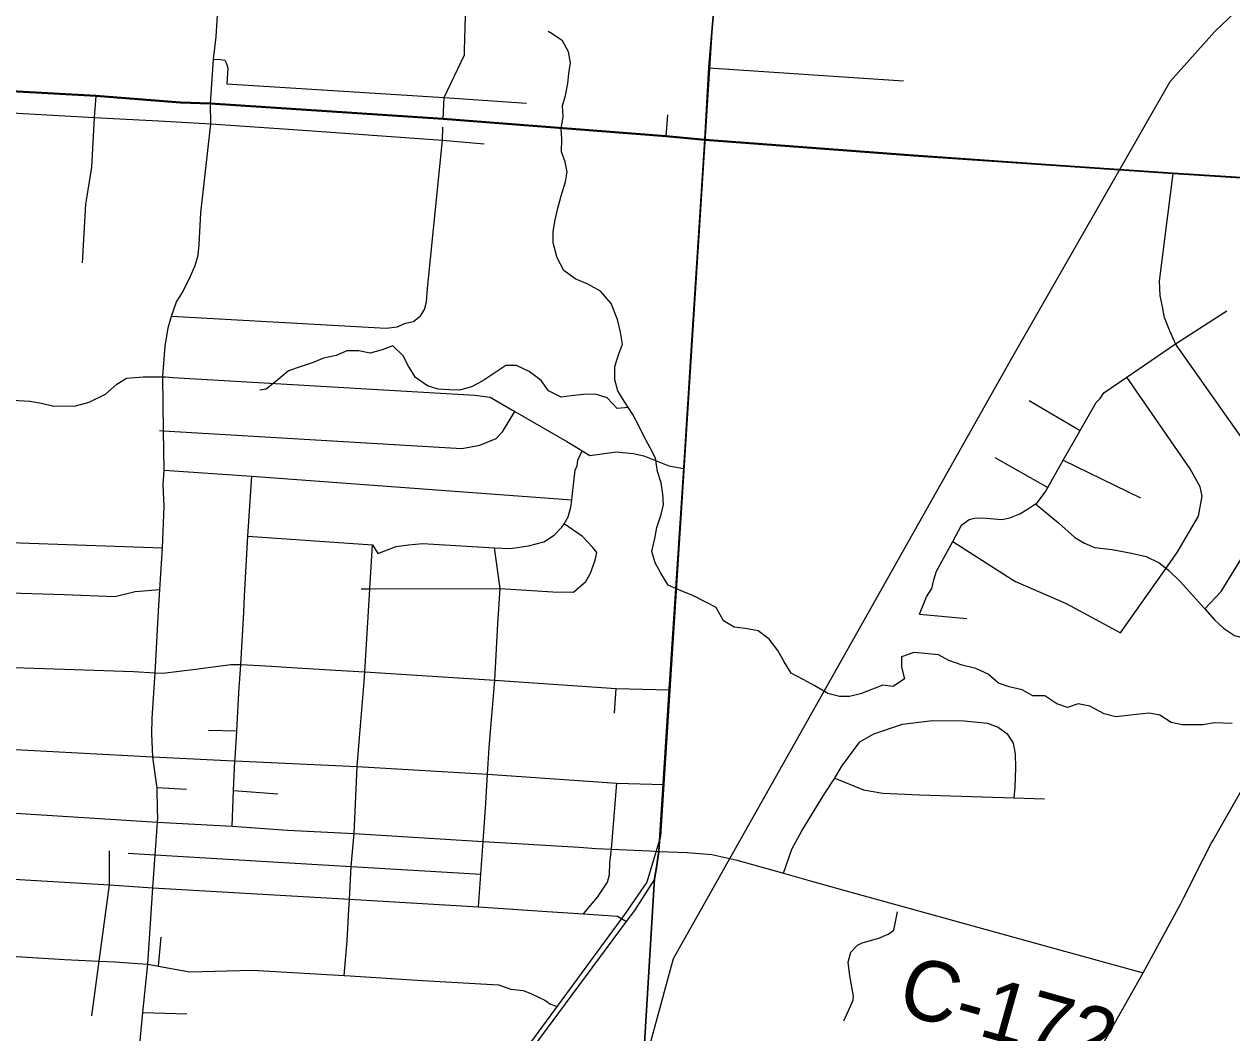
# Model space of a CAD drawing. Extents: x 0 to 34, y 0 to 22.
# Drawn here: x 3.011 to 4.152, y 15.572 to 16.524 of the extents above; entities that cross this region are included whole.
import ezdxf

# ---------------------------------------------------------------- set-up
doc = ezdxf.new("R2010")
doc.units = 0
for name, color, linetype in [('GM_X_City_Street', 7, 'Continuous'), ('GM_X_County_Road', 7, 'Continuous'), ('GM_X_County_Road_Text', 7, 'Continuous'), ('GM_X_Minor_River', 7, 'Continuous'), ('GM_X_Rail_Line', 7, 'Continuous'), ('GM_X_State_Route', 7, 'Continuous'), ('GM_X_Township_Road', 7, 'Continuous')]:
    doc.layers.add(name, color=color, linetype=linetype)

msp = doc.modelspace()

# ---------------------------------------------------------------- linework, layer by layer
at = {"layer": 'GM_X_City_Street'}
for p, q in [((3.4269, 16.4995), (3.428, 16.5321)), ((3.0775, 16.4361), (3.079, 16.4564)), ((3.6175, 16.4183), (3.6189, 16.4387)), ((4.0986, 16.2224), (4.1471, 16.2536)), ((3.9604, 16.1688), (4.0084, 16.1404)), ((3.9278, 16.1152), (3.9779, 16.0868)), ((3.9925, 16.1125), (4.0656, 16.0771)), ((3.8568, 15.9672), (3.9015, 15.963)), ((3.3133, 15.6258), (3.316, 15.6584))]:
    msp.add_line(p, q, dxfattribs=at)
for points in [[(3.1869, 16.4491), (3.1898, 16.4914), (3.1922, 16.5124), (3.194, 16.5377), (3.1953, 16.5587), (3.1958, 16.5715), (3.1963, 16.5771), (3.1976, 16.5817), (3.1996, 16.5875), (3.2022, 16.5935), (3.2063, 16.5999), (3.2107, 16.6054), (3.2295, 16.6239), (3.2699, 16.661), (3.3316, 16.7186), (3.3479, 16.7335), (3.3529, 16.7386), (3.3582, 16.7457), (3.3587, 16.7466)], [(3.4067, 16.4347), (3.4077, 16.4551), (3.4268, 16.4954), (3.4269, 16.4995)], [(3.1898, 16.4914), (3.1965, 16.4909), (3.2004, 16.4903), (3.202, 16.4871), (3.2033, 16.4827), (3.2024, 16.4681), (3.4077, 16.4551), (3.4854, 16.4498)], [(2.8272, 16.4501), (2.8851, 16.4478), (3.0099, 16.44), (3.0775, 16.4361), (3.1074, 16.4346), (3.1381, 16.433), (3.1874, 16.4301), (3.2697, 16.4245), (3.406, 16.4147), (3.4454, 16.4112)], [(3.138, 15.9699), (3.1391, 15.9904), (3.1417, 16.0298), (3.1432, 16.0688), (3.1422, 16.0892), (3.1431, 16.103), (3.1426, 16.1403), (3.1419, 16.1912), (3.1419, 16.192), (3.144, 16.2201), (3.147, 16.2375), (3.1501, 16.2486), (3.1547, 16.262), (3.1606, 16.271), (3.1681, 16.2864), (3.1725, 16.2965), (3.1754, 16.3063), (3.1764, 16.3162), (3.1778, 16.3461), (3.1874, 16.4301), (3.1869, 16.4491)], [(3.0698, 16.3582), (3.075, 16.3891), (3.0775, 16.4361)], [(3.3787, 16.2435), (3.3853, 16.2487), (3.3892, 16.2547), (3.3909, 16.2622), (3.3919, 16.2747), (3.406, 16.4147), (3.4063, 16.427)], [(4.1263, 15.972), (4.1418, 15.9884), (4.1819, 16.054), (4.1887, 16.0728), (4.1886, 16.0823), (4.1879, 16.0892), (4.1862, 16.0972), (4.1789, 16.1087), (4.1679, 16.1242), (4.0986, 16.2224), (4.0922, 16.237), (4.0882, 16.2473), (4.0865, 16.2557), (4.0841, 16.2679), (4.0836, 16.2816), (4.0963, 16.3832)], [(3.0661, 16.2988), (3.0691, 16.3543), (3.0698, 16.3582)], [(3.1501, 16.2486), (3.3528, 16.2372), (3.3634, 16.2385), (3.3711, 16.2418), (3.3787, 16.2435)], [(3.8568, 15.9672), (3.8615, 15.9788), (3.8634, 15.9835), (3.8683, 15.9912), (3.8704, 15.9995), (3.8728, 16.0078), (3.8881, 16.0358), (3.8965, 16.051), (3.9038, 16.0565), (3.9087, 16.0579), (3.9163, 16.0582), (3.9345, 16.0566), (3.9421, 16.058), (3.9516, 16.0619), (3.9589, 16.0663), (3.9664, 16.0714), (3.9682, 16.0726), (3.976, 16.0834), (3.9779, 16.0868), (3.9925, 16.1125), (4.0084, 16.1404), (4.0236, 16.1671), (4.0275, 16.1708), (4.031, 16.176), (4.0527, 16.1909), (4.0986, 16.2224)], [(2.8281, 16.1733), (2.8316, 16.1766), (2.8376, 16.1773), (2.8456, 16.1779), (3.0163, 16.1681), (3.0273, 16.1664), (3.039, 16.1635), (3.0594, 16.1638), (3.0724, 16.1673), (3.0877, 16.175), (3.0985, 16.1842), (3.1077, 16.1901), (3.1233, 16.1913), (3.1419, 16.1912), (3.1426, 16.1912), (3.1446, 16.1911), (3.1515, 16.1907)], [(3.1515, 16.1907), (3.4367, 16.1739), (3.4511, 16.1721), (3.4604, 16.1666), (3.4744, 16.1586), (3.5237, 16.1303), (3.5361, 16.1225), (3.538, 16.1213), (3.5454, 16.117), (3.5702, 16.1205), (3.5862, 16.1189), (3.5962, 16.1167), (3.6058, 16.1127), (3.62, 16.1071), (3.6342, 16.1048)], [(4.0467, 15.9494), (4.0897, 16.0105), (4.1002, 16.0254), (4.1202, 16.0595), (4.1237, 16.0784), (4.122, 16.0872), (4.1125, 16.1044), (4.0527, 16.1909)], [(3.1387, 16.1405), (3.1426, 16.1403), (3.4243, 16.1237), (3.4414, 16.1268), (3.4567, 16.1329), (3.4629, 16.1392), (3.4744, 16.1586)], [(3.2222, 16.0406), (3.34, 16.0327), (3.3449, 16.0244), (3.3624, 16.0309), (3.3739, 16.0326), (3.3871, 16.0338), (3.4552, 16.0298), (3.47, 16.029), (3.4875, 16.0316), (3.502, 16.0355), (3.5116, 16.0418), (3.519, 16.0492), (3.521, 16.0525), (3.5249, 16.0589), (3.5273, 16.068), (3.5283, 16.0751), (3.5291, 16.0812), (3.5315, 16.1032), (3.5335, 16.1073), (3.534, 16.1126), (3.538, 16.1213)], [(3.1431, 16.103), (3.2259, 16.0973), (3.5283, 16.0751)], [(3.2184, 15.9687), (3.2192, 15.9844), (3.2222, 16.0406), (3.2259, 16.0973)], [(3.9664, 16.0714), (3.9882, 16.0532), (4.0035, 16.0396), (4.0125, 16.0341), (4.0222, 16.0301), (4.0389, 16.0282), (4.057, 16.0248), (4.0709, 16.0214), (4.0833, 16.0155), (4.089, 16.011), (4.0897, 16.0105), (4.0922, 16.0084), (4.103, 15.998), (4.1263, 15.972), (4.1356, 15.9616), (4.1438, 15.9538), (4.1542, 15.9468), (4.1663, 15.9438), (4.1746, 15.9429), (4.1997, 15.9465), (4.2058, 15.9468), (4.2122, 15.9455), (4.2368, 15.9393)], [(3.3293, 15.991), (3.3374, 15.991), (3.4605, 15.9913), (3.5104, 15.9881), (3.5298, 15.9878), (3.5414, 15.9978), (3.5461, 16.0057), (3.5505, 16.0181), (3.5518, 16.0253), (3.5481, 16.03), (3.5385, 16.0404), (3.521, 16.0525)], [(2.8209, 16.0408), (2.9795, 16.0354), (3.1417, 16.0298)], [(3.3358, 15.9647), (3.3374, 15.991), (3.34, 16.0327)], [(3.4583, 15.958), (3.4605, 15.9913), (3.4552, 16.0298)], [(3.8881, 16.0358), (3.9443, 15.9998), (3.9476, 15.9979), (3.9953, 15.9771), (4.0467, 15.9494)], [(2.8235, 15.9931), (2.9766, 15.988), (3.0492, 15.9858), (3.0966, 15.9839), (3.1159, 15.9886), (3.1391, 15.9904)], [(3.3244, 15.7949), (3.3256, 15.8231), (3.3275, 15.8466)], [(3.4471, 15.7885), (3.4487, 15.8161), (3.4502, 15.8411)], [(3.2027, 15.829), (3.2101, 15.8287), (3.3256, 15.8231), (3.4487, 15.8161), (3.5708, 15.8076), (3.6148, 15.8062)], [(3.167, 15.6292), (3.2266, 15.6309), (3.3133, 15.6258), (3.314, 15.6258), (3.3873, 15.6212), (3.4591, 15.6171), (3.4707, 15.6129), (3.4824, 15.6115), (3.4895, 15.6087), (3.4974, 15.6051), (3.5027, 15.6024), (3.5083, 15.5988), (3.5135, 15.5968)]]:
    msp.add_lwpolyline(points, dxfattribs=at)
at = {"layer": 'GM_X_County_Road'}
msp.add_line((3.5657, 15.7451), (3.6017, 15.7434), dxfattribs=at)
for points in [[(2.884, 16.4676), (3.0788, 16.4569), (3.1585, 16.4507), (3.1867, 16.4496), (3.4065, 16.4352), (3.6172, 16.4188), (3.654, 16.4154), (3.6577, 16.4837), (3.663, 16.546), (3.6669, 16.6092), (3.6708, 16.6723), (3.6747, 16.7338), (3.6783, 16.7921), (3.682, 16.8509), (3.6854, 16.9064), (3.686, 16.9146), (3.6886, 16.9563), (3.6945, 17.0525), (3.6989, 17.1221), (3.6998, 17.1375), (3.7021, 17.1741), (3.7063, 17.2218), (3.7066, 17.225), (3.7101, 17.3019)], [(3.7101, 17.3019), (3.7066, 17.225), (3.7063, 17.2218), (3.7021, 17.1741), (3.6998, 17.1375), (3.6989, 17.1221), (3.6945, 17.0525), (3.6886, 16.9563), (3.686, 16.9146), (3.6854, 16.9064), (3.682, 16.8509), (3.6783, 16.7921), (3.6747, 16.7338), (3.6708, 16.6723), (3.6669, 16.6092), (3.663, 16.546), (3.6577, 16.4837), (3.654, 16.4154), (3.8512, 16.4005), (3.9805, 16.3916), (4.0961, 16.3837), (4.4809, 16.3594)], [(3.6542, 16.4148), (3.6579, 16.4832), (3.6632, 16.5454), (3.6671, 16.6087), (3.6711, 16.6718), (3.6749, 16.7333), (3.6785, 16.7915), (3.6822, 16.8503), (3.6857, 16.9058), (3.6862, 16.914), (3.6888, 16.9558), (3.6948, 17.052), (3.6991, 17.1215), (3.7001, 17.1369), (3.7024, 17.1735), (3.7065, 17.2213), (3.7068, 17.2244), (3.7103, 17.3014)], [(2.1, 16.5138), (2.2437, 16.5027), (2.3644, 16.4926), (2.533, 16.4821), (2.7036, 16.4747), (2.8842, 16.467), (3.079, 16.4564), (3.1587, 16.4501), (3.1869, 16.4491), (3.4067, 16.4347), (3.6175, 16.4183), (3.6542, 16.4148)], [(5.4989, 16.2977), (5.2615, 16.3089), (5.0301, 16.3238), (4.7825, 16.3404), (4.4809, 16.3594), (4.0961, 16.3837), (3.9805, 16.3916), (3.8512, 16.4005), (3.654, 16.4154), (3.6418, 16.2257), (3.634, 16.1053), (3.6204, 15.8961), (3.6146, 15.8068), (3.6105, 15.7435), (3.6083, 15.7281), (3.6065, 15.7173), (3.5547, 14.8664), (3.5412, 14.6736), (3.5067, 14.1788), (3.5033, 14.1), (8.2619, 14.1)], [(3.6168, 15.836), (3.6206, 15.8956), (3.6342, 16.1048), (3.642, 16.2252), (3.6542, 16.4148)], [(3.6542, 16.4148), (3.8515, 16.3999), (3.9807, 16.3911), (4.0963, 16.3832), (4.4811, 16.3588)], [(3.4766, 15.5374), (3.5224, 15.599), (3.5801, 15.6767), (3.5879, 15.6873), (3.6067, 15.7167), (3.6085, 15.7276), (3.6107, 15.7429), (3.6148, 15.8062), (3.6168, 15.836)], [(2.7826, 15.7922), (2.7921, 15.7915), (2.8726, 15.7865), (2.9627, 15.7816), (3.1368, 15.7707), (3.2073, 15.7668), (3.2598, 15.7632), (3.3228, 15.7599), (3.4447, 15.7525), (3.5351, 15.7469)], [(3.5351, 15.7469), (3.5512, 15.7459), (3.5657, 15.7451)], [(3.6017, 15.7434), (3.6107, 15.7429), (3.6374, 15.7419), (3.6605, 15.74), (3.6834, 15.735), (3.7283, 15.7224), (3.7546, 15.715), (3.7773, 15.7087), (3.7783, 15.7084)], [(3.7783, 15.7084), (3.9754, 15.6538), (4.0681, 15.6282)]]:
    msp.add_lwpolyline(points, dxfattribs=at)
msp.add_lwpolyline([(2.1, 16.5143), (2.1, 14.1), (3.5033, 14.1), (3.5067, 14.1788), (3.5412, 14.6736), (3.5547, 14.8664), (3.6065, 15.7173), (3.6083, 15.7281), (3.6105, 15.7435), (3.6146, 15.8068), (3.6204, 15.8961), (3.634, 16.1053), (3.6418, 16.2257), (3.654, 16.4154), (3.6172, 16.4188), (3.4065, 16.4352), (3.1867, 16.4496), (3.1585, 16.4507), (3.0788, 16.4569), (2.884, 16.4676), (2.7034, 16.4752), (2.5328, 16.4826), (2.3641, 16.4932), (2.2435, 16.5033)], close=True, dxfattribs=at)
at = {"layer": 'GM_X_Minor_River'}
for points in [[(3.6923, 15.9536), (3.6817, 15.9549), (3.6715, 15.9607), (3.6648, 15.9733), (3.655, 15.9783), (3.6433, 15.9845), (3.6316, 15.9891), (3.6192, 15.9946), (3.6124, 16.0057), (3.6072, 16.0156), (3.6039, 16.0262), (3.6067, 16.0384), (3.6087, 16.049), (3.6126, 16.0611), (3.6149, 16.0706), (3.6143, 16.0805), (3.6128, 16.0911), (3.6091, 16.1018), (3.6074, 16.1143), (3.6022, 16.1243), (3.5962, 16.1353), (3.5914, 16.1456), (3.5861, 16.1555), (3.5779, 16.1682), (3.5719, 16.1781), (3.569, 16.1884), (3.5691, 16.2009), (3.5723, 16.2119), (3.5761, 16.2221), (3.5743, 16.2335), (3.5714, 16.2453), (3.5655, 16.2606), (3.5554, 16.2721), (3.5433, 16.2786), (3.5316, 16.2837), (3.5207, 16.2918), (3.5144, 16.3036), (3.5107, 16.3177), (3.5108, 16.3283), (3.5124, 16.3378), (3.5148, 16.3492), (3.5183, 16.3621), (3.5222, 16.3753), (3.5238, 16.3848), (3.522, 16.3943), (3.5187, 16.4038), (3.5188, 16.416), (3.5181, 16.4255), (3.5201, 16.4372), (3.5195, 16.4471), (3.5222, 16.457), (3.5246, 16.4683), (3.5254, 16.4778), (3.527, 16.4877), (3.5252, 16.4983), (3.5196, 16.5087), (3.5099, 16.5152), (3.5061, 16.5175)], [(3.5818, 16.1622), (3.571, 16.1614), (3.5617, 16.1714), (3.5507, 16.1749), (3.5393, 16.1746), (3.5276, 16.1732), (3.5181, 16.1721), (3.5064, 16.1779), (3.4993, 16.1879), (3.488, 16.1964), (3.4759, 16.2018), (3.466, 16.2019), (3.4443, 16.1876), (3.4336, 16.1817), (3.4222, 16.1787), (3.4128, 16.1788), (3.4022, 16.1797), (3.392, 16.1828), (3.3807, 16.1905), (3.3739, 16.2012), (3.3691, 16.2111), (3.3593, 16.2204), (3.3491, 16.2166), (3.3377, 16.2137), (3.3271, 16.2157), (3.3157, 16.2158), (3.3058, 16.2114), (3.2937, 16.2088), (3.2841, 16.2047), (3.2716, 16.2007), (3.2606, 16.197), (3.2506, 16.1883), (3.2396, 16.1797), (3.2335, 16.1786)], [(4.152, 15.8639), (4.1353, 15.8644), (4.1243, 15.8626), (4.1144, 15.8627), (4.105, 15.8624), (4.0944, 15.8648), (4.0838, 15.8717), (4.0736, 15.8737), (4.0619, 15.8723), (4.0421, 15.8702), (4.0312, 15.873), (4.0176, 15.8803), (4.0066, 15.8823), (3.9967, 15.879), (3.9865, 15.8825), (3.9752, 15.8898), (3.9639, 15.8899), (3.9537, 15.8957), (3.9416, 15.8985), (3.9314, 15.902), (3.9216, 15.9105), (3.9099, 15.9159), (3.897, 15.919), (3.8846, 15.9233), (3.8748, 15.9288), (3.8619, 15.93), (3.8513, 15.9309), (3.8399, 15.9268), (3.8398, 15.9169), (3.8427, 15.9059), (3.832, 15.8988), (3.8222, 15.9), (3.8123, 15.8963), (3.8009, 15.8918), (3.7906, 15.8893), (3.7812, 15.8894), (3.7702, 15.8921), (3.7578, 15.8995), (3.7468, 15.9053), (3.7355, 15.9115), (3.7288, 15.9221), (3.7228, 15.9328), (3.7146, 15.9436), (3.7044, 15.9512), (3.6923, 15.9536)]]:
    msp.add_lwpolyline(points, dxfattribs=at)
at = {"layer": 'GM_X_Rail_Line'}
for points in [[(3.7202, 17.4495), (3.6121, 15.7571), (3.5991, 15.7141), (3.5781, 15.6833), (3.3718, 15.4026), (3.2933, 15.2964), (3.27, 15.2612), (3.26, 15.2394), (3.2447, 15.1962), (3.2204, 15.1356), (3.1206, 14.8429), (3.107, 14.7951), (3.0878, 14.7358), (3.0717, 14.6527), (3.0679, 14.583), (3.0599, 14.4798), (3.0531, 14.3964), (3.0341, 14.1)], [(3.2263, 14.1), (3.3201, 14.4671), (3.4798, 15.0811), (3.5889, 15.5111), (3.6244, 15.6418), (3.9439, 16.2089), (4.0935, 16.4703), (4.1354, 16.5172), (4.1886, 16.568), (4.5538, 16.8382), (4.6413, 16.9169), (4.6831, 16.9702), (4.73, 17.0374), (4.7604, 17.097), (4.7896, 17.177), (4.8023, 17.2505), (4.8213, 17.366)]]:
    msp.add_lwpolyline(points, dxfattribs=at)
at = {"layer": 'GM_X_State_Route'}
msp.add_line((4.1064, 15.6994), (4.1248, 15.7356), dxfattribs=at)
for points in [[(4.1341, 15.7536), (4.1589, 15.7966), (4.1642, 15.8063)], [(4.1248, 15.7356), (4.1326, 15.751), (4.1341, 15.7536)], [(4.0681, 15.6282), (4.1032, 15.6931), (4.1064, 15.6994)], [(3.9411, 15.4018), (3.9506, 15.4193), (3.9861, 15.4829), (4.0275, 15.5564), (4.0681, 15.6282)]]:
    msp.add_lwpolyline(points, dxfattribs=at)
at = {"layer": 'GM_X_Township_Road'}
for p, q in [((3.6579, 16.4832), (3.8415, 16.4708)), ((3.2155, 15.9196), (3.2449, 15.9179)), ((3.2117, 15.8568), (3.2142, 15.8984)), ((3.3275, 15.8466), (3.332, 15.9032)), ((3.5687, 15.8735), (3.5703, 15.8968)), ((3.185, 15.8576), (3.2117, 15.8568)), ((3.1366, 15.8034), (3.1644, 15.8018)), ((3.2088, 15.8004), (3.2506, 15.7974)), ((3.316, 15.6584), (3.3177, 15.688)), ((3.1378, 15.6346), (3.1403, 15.6621)), ((3.1231, 15.5909), (3.1646, 15.5897))]:
    msp.add_line(p, q, dxfattribs=at)
for points in [[(3.137, 15.7819), (3.1366, 15.8034), (3.1361, 15.8069), (3.1326, 15.8322), (3.1315, 15.8539), (3.132, 15.8688), (3.1346, 15.9118), (3.138, 15.9699)], [(3.2142, 15.8984), (3.2144, 15.9015), (3.2155, 15.9196), (3.2184, 15.9687)], [(3.332, 15.9032), (3.3328, 15.9126), (3.3358, 15.9647)], [(3.4502, 15.8411), (3.4555, 15.9046), (3.4583, 15.958)], [(2.8166, 15.9227), (2.8322, 15.9221), (2.8731, 15.9208), (2.9716, 15.9176), (3.0492, 15.915), (3.1141, 15.9128), (3.1346, 15.9118), (3.1418, 15.9115), (3.1728, 15.915), (3.2063, 15.9194), (3.2155, 15.9196)], [(3.2449, 15.9179), (3.2586, 15.9171), (3.3052, 15.9142), (3.3328, 15.9126), (3.4555, 15.9046), (3.5703, 15.8968), (3.6206, 15.8956)], [(3.7283, 15.7224), (3.7362, 15.745), (3.7455, 15.7623), (3.7671, 15.7974), (3.7768, 15.8122), (3.7833, 15.8235), (3.8005, 15.8465), (3.8136, 15.8539), (3.8408, 15.8632)], [(3.8408, 15.8632), (3.8692, 15.8665), (3.8991, 15.8663), (3.9209, 15.864), (3.9311, 15.8604), (3.9396, 15.8539), (3.9452, 15.8453), (3.9472, 15.8353), (3.9476, 15.8219), (3.9468, 15.8038), (3.9459, 15.7936)], [(2.71, 15.8568), (2.8052, 15.8506), (2.967, 15.841), (3.1326, 15.8322), (3.2027, 15.829)], [(3.2073, 15.7668), (3.2088, 15.8004), (3.2101, 15.8287), (3.2102, 15.8305), (3.2117, 15.8568)], [(3.5393, 15.684), (3.5527, 15.6998), (3.5621, 15.714), (3.564, 15.7209), (3.5643, 15.7323), (3.5657, 15.7451), (3.5708, 15.8076)], [(3.7768, 15.8122), (3.804, 15.8011), (3.822, 15.7979), (3.8567, 15.7964), (3.9459, 15.7936), (3.9748, 15.7928)], [(3.3218, 15.7495), (3.3228, 15.7599), (3.3244, 15.7949)], [(3.103, 15.3881), (3.1059, 15.4172), (3.109, 15.449), (3.1127, 15.486), (3.1164, 15.523), (3.1198, 15.5574), (3.1231, 15.5909), (3.1277, 15.6365), (3.1325, 15.7086), (3.1347, 15.7399), (3.1368, 15.7707), (3.1371, 15.7755), (3.137, 15.7819)], [(3.4403, 15.6907), (3.4422, 15.7215), (3.4447, 15.7525), (3.4471, 15.7885)], [(3.3177, 15.688), (3.3183, 15.6979), (3.3199, 15.7287), (3.3218, 15.7495)], [(2.6639, 15.7369), (2.7887, 15.7295), (2.9582, 15.7193), (3.0914, 15.7113), (3.1325, 15.7086), (3.3183, 15.6979), (3.4403, 15.6907), (3.505, 15.6861), (3.5393, 15.684)], [(3.075, 15.5877), (3.0818, 15.6394), (3.0914, 15.7113), (3.0916, 15.7436)], [(3.1093, 15.7414), (3.1347, 15.7399), (3.2087, 15.7354), (3.3199, 15.7287), (3.4422, 15.7215)], [(3.5393, 15.684), (3.5716, 15.6818), (3.5801, 15.6767)], [(3.7854, 15.583), (3.7917, 15.5969), (3.794, 15.6026), (3.7945, 15.6064), (3.7909, 15.6254), (3.7895, 15.6384), (3.7919, 15.6479), (3.7981, 15.6546), (3.8027, 15.6568), (3.8183, 15.6612), (3.8271, 15.6649), (3.8325, 15.6686), (3.836, 15.686)], [(2.5646, 15.6678), (2.5768, 15.6697), (2.6591, 15.6647), (2.7831, 15.6569), (2.953, 15.647), (3.0492, 15.641), (3.0818, 15.6394), (3.0965, 15.6387), (3.1094, 15.6378)], [(3.1094, 15.6378), (3.1277, 15.6365), (3.1378, 15.6346), (3.167, 15.6292)]]:
    msp.add_lwpolyline(points, dxfattribs=at)

# ---------------------------------------------------------------- texts
at = {"layer": 'GM_X_County_Road_Text'}
msp.add_text('C-172', height=0.05682, rotation=344.3586, dxfattribs=at).set_placement((3.8337, 15.5913))

doc.saveas('drawing.dxf')
